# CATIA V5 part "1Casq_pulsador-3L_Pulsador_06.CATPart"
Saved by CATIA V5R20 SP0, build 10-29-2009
Part number: 1Casq_pulsador-3L_Pulsador_06
Revision: ANY
Definition: UNKNOWN
Nomenclature: 1Casq_pulsador-3L_Pulsador_06
Source: Unknown
Bounding box of the stored display mesh (mm): x -5.3 to 5.3, y 0 to 15.3, z -5.3 to 5.3
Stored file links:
  C:\Users\Utente\Desktop\IO LAVORO\3D X SITO CF\CUMSA\3D files BE\BE 031115\1Casq_pulsador-3L_Pulsador_06.CATPart
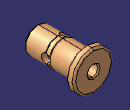
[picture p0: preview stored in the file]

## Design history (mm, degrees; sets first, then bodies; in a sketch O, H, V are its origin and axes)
Body1 "MatrizC1" (main body)
  Solid1: solid without history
